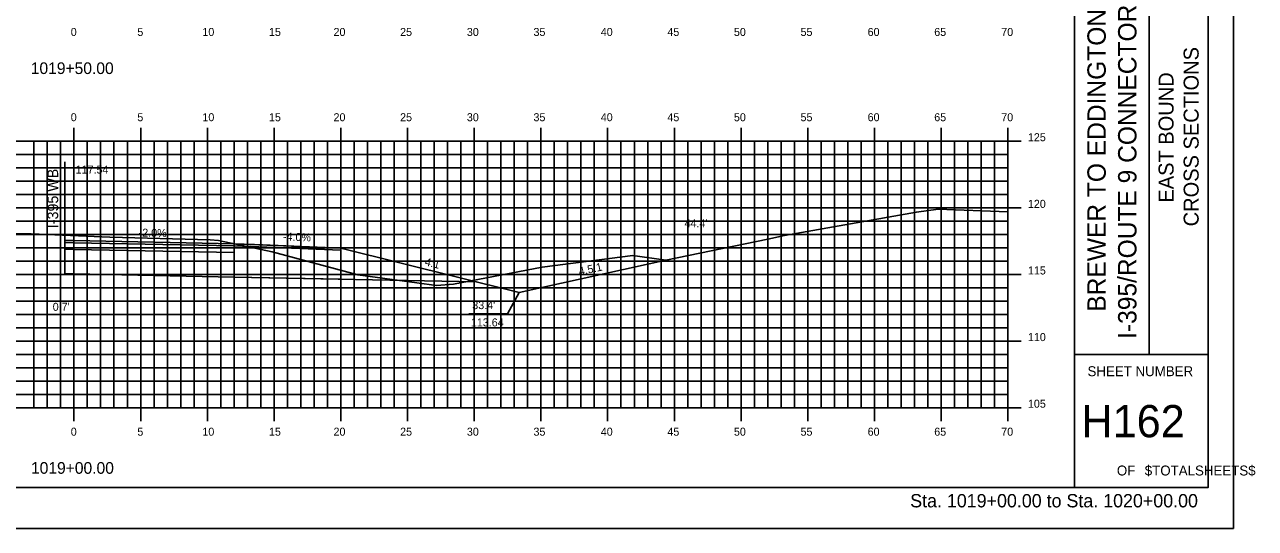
# Model space of a CAD drawing. Extents: x 853734 to 853906, y 365624 to 365734.
# Drawn here: x 853813.6 to 853905.9, y 365624 to 365661.8 of the extents above; entities that cross this region are included whole.
import ezdxf

# ---------------------------------------------------------------- set-up
doc = ezdxf.new("R2010")
doc.units = 0
for name, color, linetype in [('ANNOTATION', 7, 'Continuous'), ('BORDER', 7, 'Continuous'), ('D_Roadway_Centerline', 7, 'Continuous'), ('D_Roadway_Centerline_Text', 7, 'Continuous'), ('D_Roadway_Edge_Shoulder', 7, 'Continuous'), ('D_Roadway_Edge_TW', 7, 'Continuous'), ('D_Roadway_FinishedGrade', 7, 'Continuous'), ('D_Roadway_Pavement', 7, 'Continuous'), ('D_Roadway_SubGrade', 7, 'Continuous'), ('D_Text_Standard', 7, 'Continuous'), ('H_V ANNOTATION', 7, 'Continuous'), ('MAJOR', 7, 'Continuous'), ('MINOR', 7, 'Continuous'), ('PLOT BOUNDARY', 7, 'Continuous'), ('S_Roadway_Centerline', 7, 'Continuous')]:
    doc.layers.add(name, color=color, linetype=linetype)

msp = doc.modelspace()

# ---------------------------------------------------------------- linework, layer by layer
at = {"layer": 'ANNOTATION'}
msp.add_lwpolyline([(853846.938, 365640.065), (853849.826, 365640.065), (853850.691, 365641.67)], dxfattribs=at)
at = {"layer": 'BORDER'}
for p, q in [((853892.331, 365627.027), (853892.331, 365732.027)), ((853897.922, 365637.03), (853897.922, 365672.03)), ((853892.331, 365637.03), (853902.331, 365637.03))]:
    msp.add_line(p, q, dxfattribs=at)
msp.add_lwpolyline([(853742.331, 365627.027), (853902.331, 365627.027), (853902.331, 365732.027), (853742.331, 365732.027)], close=True, dxfattribs=at)
at = {"layer": 'D_Roadway_Centerline'}
for p, q in [((853837.331, 365645.01), (853850.691, 365641.67)), ((853850.691, 365641.67), (853861.699, 365644.103)), ((853829.331, 365642.83), (853847.505, 365642.466))]:
    msp.add_line(p, q, dxfattribs=at)
msp.add_lwpolyline([(853816.655, 365645.584), (853817.235, 365645.572), (853817.331, 365645.57), (853817.332, 365645.57), (853829.331, 365645.33), (853830.854, 365645.269), (853837.326, 365645.01), (853837.331, 365645.01)], dxfattribs=at)
at = {"layer": 'D_Roadway_Edge_Shoulder'}
for points in [[(853817.331, 365645.57), (853816.655, 365645.584), (853816.655, 365645.417), (853817.331, 365645.403)], [(853829.331, 365645.33), (853837.331, 365645.01), (853837.331, 365644.843), (853829.331, 365645.163)]]:
    msp.add_lwpolyline(points, close=True, dxfattribs=at)
at = {"layer": 'D_Roadway_Edge_TW'}
msp.add_lwpolyline([(853817.331, 365645.57), (853829.331, 365645.33), (853829.331, 365645.163), (853817.331, 365645.403)], close=True, dxfattribs=at)
msp.add_lwpolyline([(853829.331, 365645.33), (853829.331, 365645.163)], dxfattribs=at)
at = {"layer": 'D_Roadway_FinishedGrade'}
for p, q in [((853816.655, 365645.584), (853816.655, 365645.334)), ((853817.331, 365645.57), (853817.331, 365645.32)), ((853829.331, 365645.33), (853829.331, 365645.08)), ((853837.331, 365645.01), (853837.331, 365644.76))]:
    msp.add_line(p, q, dxfattribs=at)
at = {"layer": 'D_Roadway_Pavement'}
for points in [[(853817.331, 365645.403), (853816.655, 365645.417), (853816.655, 365644.917), (853817.331, 365644.903)], [(853817.331, 365645.403), (853829.331, 365645.163), (853829.331, 365644.663), (853817.331, 365644.903)]]:
    msp.add_lwpolyline(points, close=True, dxfattribs=at)
msp.add_lwpolyline([(853829.331, 365645.163), (853829.331, 365644.663)], dxfattribs=at)
msp.add_lwpolyline([(853829.331, 365645.163), (853829.331, 365644.663)], dxfattribs=at)
at = {"layer": 'D_Roadway_SubGrade'}
msp.add_line((853816.655, 365651.488), (853816.655, 365643.084), dxfattribs=at)
for points in [[(853817.331, 365644.903), (853816.655, 365644.917), (853816.655, 365645.417), (853816.655, 365645.584), (853816.655, 365643.084), (853817.331, 365643.07)], [(853817.331, 365644.903), (853829.331, 365644.663), (853829.331, 365642.83), (853817.331, 365643.07)], [(853829.331, 365644.663), (853829.331, 365645.163), (853837.331, 365644.843), (853837.331, 365645.01), (853837.331, 365642.67), (853829.331, 365642.83)]]:
    msp.add_lwpolyline(points, close=True, dxfattribs=at)
msp.add_lwpolyline([(853829.331, 365644.663), (853829.331, 365642.83)], dxfattribs=at)
at = {"layer": 'MAJOR'}
for p, q in [((853817.331, 365654.029), (853817.331, 365653.027)), ((853822.331, 365654.029), (853822.331, 365653.027)), ((853827.331, 365654.029), (853827.331, 365653.027)), ((853832.331, 365654.029), (853832.331, 365653.027)), ((853837.331, 365654.029), (853837.331, 365653.027)), ((853842.331, 365654.029), (853842.331, 365653.027)), ((853847.331, 365654.029), (853847.331, 365653.027)), ((853852.331, 365654.029), (853852.331, 365653.027)), ((853857.331, 365654.029), (853857.331, 365653.027)), ((853862.331, 365654.029), (853862.331, 365653.027)), ((853867.331, 365654.029), (853867.331, 365653.027)), ((853872.331, 365654.029), (853872.331, 365653.027)), ((853877.331, 365654.029), (853877.331, 365653.027)), ((853882.331, 365654.029), (853882.331, 365653.027)), ((853887.331, 365654.029), (853887.331, 365653.027)), ((853747.331, 365653.027), (853887.331, 365653.027)), ((853747.331, 365653.027), (853887.331, 365653.027)), ((853817.331, 365633.027), (853817.331, 365653.027)), ((853822.331, 365633.027), (853822.331, 365653.027)), ((853827.331, 365633.027), (853827.331, 365653.027)), ((853832.331, 365633.027), (853832.331, 365653.027)), ((853837.331, 365633.027), (853837.331, 365653.027)), ((853842.331, 365633.027), (853842.331, 365653.027)), ((853847.331, 365633.027), (853847.331, 365653.027)), ((853852.331, 365633.027), (853852.331, 365653.027)), ((853857.331, 365633.027), (853857.331, 365653.027)), ((853862.331, 365633.027), (853862.331, 365653.027)), ((853867.331, 365633.027), (853867.331, 365653.027)), ((853872.331, 365633.027), (853872.331, 365653.027)), ((853877.331, 365633.027), (853877.331, 365653.027)), ((853882.331, 365633.027), (853882.331, 365653.027)), ((853888.333, 365653.027), (853886.329, 365653.027)), ((853887.331, 365633.027), (853887.331, 365653.027)), ((853887.331, 365633.027), (853887.331, 365653.027)), ((853747.331, 365648.027), (853887.331, 365648.027)), ((853888.333, 365648.027), (853886.329, 365648.027)), ((853747.331, 365643.027), (853887.331, 365643.027)), ((853888.333, 365643.027), (853886.329, 365643.027)), ((853747.331, 365638.027), (853887.331, 365638.027)), ((853888.333, 365638.027), (853886.329, 365638.027)), ((853747.331, 365633.027), (853887.331, 365633.027)), ((853747.331, 365633.027), (853887.331, 365633.027)), ((853817.331, 365632.025), (853817.331, 365633.027)), ((853822.331, 365632.025), (853822.331, 365633.027)), ((853827.331, 365632.025), (853827.331, 365633.027)), ((853832.331, 365632.025), (853832.331, 365633.027)), ((853837.331, 365632.025), (853837.331, 365633.027)), ((853842.331, 365632.025), (853842.331, 365633.027)), ((853847.331, 365632.025), (853847.331, 365633.027)), ((853852.331, 365632.025), (853852.331, 365633.027)), ((853857.331, 365632.025), (853857.331, 365633.027)), ((853862.331, 365632.025), (853862.331, 365633.027)), ((853867.331, 365632.025), (853867.331, 365633.027)), ((853872.331, 365632.025), (853872.331, 365633.027)), ((853877.331, 365632.025), (853877.331, 365633.027)), ((853882.331, 365632.025), (853882.331, 365633.027)), ((853888.333, 365633.027), (853886.329, 365633.027)), ((853887.331, 365632.025), (853887.331, 365633.027))]:
    msp.add_line(p, q, dxfattribs=at)
at = {"layer": 'MINOR'}
for p, q in [((853814.331, 365633.027), (853814.331, 365653.027)), ((853815.331, 365633.027), (853815.331, 365653.027)), ((853816.331, 365633.027), (853816.331, 365653.027)), ((853818.331, 365633.027), (853818.331, 365653.027)), ((853819.331, 365633.027), (853819.331, 365653.027)), ((853820.331, 365633.027), (853820.331, 365653.027)), ((853821.331, 365633.027), (853821.331, 365653.027)), ((853823.331, 365633.027), (853823.331, 365653.027)), ((853824.331, 365633.027), (853824.331, 365653.027)), ((853825.331, 365633.027), (853825.331, 365653.027)), ((853826.331, 365633.027), (853826.331, 365653.027)), ((853828.331, 365633.027), (853828.331, 365653.027)), ((853829.331, 365633.027), (853829.331, 365653.027)), ((853830.331, 365633.027), (853830.331, 365653.027)), ((853831.331, 365633.027), (853831.331, 365653.027)), ((853833.331, 365633.027), (853833.331, 365653.027)), ((853834.331, 365633.027), (853834.331, 365653.027)), ((853835.331, 365633.027), (853835.331, 365653.027)), ((853836.331, 365633.027), (853836.331, 365653.027)), ((853838.331, 365633.027), (853838.331, 365653.027)), ((853839.331, 365633.027), (853839.331, 365653.027)), ((853840.331, 365633.027), (853840.331, 365653.027)), ((853841.331, 365633.027), (853841.331, 365653.027)), ((853843.331, 365633.027), (853843.331, 365653.027)), ((853844.331, 365633.027), (853844.331, 365653.027)), ((853845.331, 365633.027), (853845.331, 365653.027)), ((853846.331, 365633.027), (853846.331, 365653.027)), ((853848.331, 365633.027), (853848.331, 365653.027)), ((853849.331, 365633.027), (853849.331, 365653.027)), ((853850.331, 365633.027), (853850.331, 365653.027)), ((853851.331, 365633.027), (853851.331, 365653.027)), ((853853.331, 365633.027), (853853.331, 365653.027)), ((853854.331, 365633.027), (853854.331, 365653.027)), ((853855.331, 365633.027), (853855.331, 365653.027)), ((853856.331, 365633.027), (853856.331, 365653.027)), ((853858.331, 365633.027), (853858.331, 365653.027)), ((853859.331, 365633.027), (853859.331, 365653.027)), ((853860.331, 365633.027), (853860.331, 365653.027)), ((853861.331, 365633.027), (853861.331, 365653.027)), ((853863.331, 365633.027), (853863.331, 365653.027)), ((853864.331, 365633.027), (853864.331, 365653.027)), ((853865.331, 365633.027), (853865.331, 365653.027)), ((853866.331, 365633.027), (853866.331, 365653.027)), ((853868.331, 365633.027), (853868.331, 365653.027)), ((853869.331, 365633.027), (853869.331, 365653.027)), ((853870.331, 365633.027), (853870.331, 365653.027)), ((853871.331, 365633.027), (853871.331, 365653.027)), ((853873.331, 365633.027), (853873.331, 365653.027)), ((853874.331, 365633.027), (853874.331, 365653.027)), ((853875.331, 365633.027), (853875.331, 365653.027)), ((853876.331, 365633.027), (853876.331, 365653.027)), ((853878.331, 365633.027), (853878.331, 365653.027)), ((853879.331, 365633.027), (853879.331, 365653.027)), ((853880.331, 365633.027), (853880.331, 365653.027)), ((853881.331, 365633.027), (853881.331, 365653.027)), ((853883.331, 365633.027), (853883.331, 365653.027)), ((853884.331, 365633.027), (853884.331, 365653.027)), ((853885.331, 365633.027), (853885.331, 365653.027)), ((853886.331, 365633.027), (853886.331, 365653.027)), ((853747.331, 365652.027), (853887.331, 365652.027)), ((853887.331, 365652.027), (853886.329, 365652.027)), ((853747.331, 365651.027), (853887.331, 365651.027)), ((853887.331, 365651.027), (853886.329, 365651.027)), ((853747.331, 365650.027), (853887.331, 365650.027)), ((853887.331, 365650.027), (853886.329, 365650.027)), ((853747.331, 365649.027), (853887.331, 365649.027)), ((853887.331, 365649.027), (853886.329, 365649.027)), ((853747.331, 365647.027), (853887.331, 365647.027)), ((853887.331, 365647.027), (853886.329, 365647.027)), ((853747.331, 365646.027), (853887.331, 365646.027)), ((853887.331, 365646.027), (853886.329, 365646.027)), ((853747.331, 365645.027), (853887.331, 365645.027)), ((853887.331, 365645.027), (853886.329, 365645.027)), ((853747.331, 365644.027), (853887.331, 365644.027)), ((853887.331, 365644.027), (853886.329, 365644.027)), ((853747.331, 365642.027), (853887.331, 365642.027)), ((853887.331, 365642.027), (853886.329, 365642.027)), ((853747.331, 365641.027), (853887.331, 365641.027)), ((853887.331, 365641.027), (853886.329, 365641.027)), ((853747.331, 365640.027), (853887.331, 365640.027)), ((853887.331, 365640.027), (853886.329, 365640.027)), ((853747.331, 365639.027), (853887.331, 365639.027)), ((853887.331, 365639.027), (853886.329, 365639.027)), ((853747.331, 365637.027), (853887.331, 365637.027)), ((853887.331, 365637.027), (853886.329, 365637.027)), ((853747.331, 365636.027), (853887.331, 365636.027)), ((853887.331, 365636.027), (853886.329, 365636.027)), ((853747.331, 365635.027), (853887.331, 365635.027)), ((853887.331, 365635.027), (853886.329, 365635.027)), ((853747.331, 365634.027), (853887.331, 365634.027)), ((853887.331, 365634.027), (853886.329, 365634.027))]:
    msp.add_line(p, q, dxfattribs=at)
at = {"layer": 'PLOT BOUNDARY'}
msp.add_lwpolyline([(853734.238, 365623.968), (853904.238, 365623.968), (853904.238, 365733.968), (853734.238, 365733.968)], close=True, dxfattribs=at)
at = {"layer": 'S_Roadway_Centerline'}
msp.add_lwpolyline([(853811.758, 365646.1), (853814.129, 365646.084), (853820.011, 365645.83), (853827.546, 365645.616), (853828.156, 365645.568), (853832.174, 365644.736), (853838.611, 365643.01), (853844.496, 365642.206), (853845.777, 365642.301), (853852.416, 365643.573), (853859.214, 365644.439), (853861.699, 365644.103), (853869.342, 365645.676), (853870.576, 365645.939), (853880.472, 365647.706), (853882.115, 365647.939), (853887.331, 365647.726)], dxfattribs=at)

# ---------------------------------------------------------------- texts
at = {"layer": 'ANNOTATION'}
for s, height, rotation, p in [('I-395 WB', 0.8, 90, (853816.148, 365646.502)), ('-2.0%', 0.6, 358.8542, (853822.175, 365645.873)), ('-4.0%', 0.6, 357.70937, (853832.986, 365645.584)), ('4:1', 0.6, 345.96376, (853843.586, 365643.721)), ('4.5:1', 0.6, 12.46619, (853855.227, 365642.946)), ("33.4' ", 0.6, 360, (853847.186, 365640.428)), ('113.64', 0.6, 360, (853847.081, 365639.128))]:
    msp.add_text(s, height=height, rotation=rotation, dxfattribs=at).set_placement(p)
at = {"layer": 'BORDER'}
for s, height, p in [('BREWER TO EDDINGTON', 1.37787, (853894.665, 365640.231)), ('I-395/ROUTE 9 CONNECTOR', 1.37787, (853896.966, 365638.192)), ('CROSS SECTIONS', 1.125, (853901.628, 365646.638)), ('EAST BOUND', 1.125, (853899.749, 365648.418))]:
    msp.add_text(s, height=height, rotation=90, dxfattribs=at).set_placement(p)
for s, height, p in [('SHEET NUMBER', 0.74527, (853893.297, 365635.393)), ('H162', 2.4194, (853892.847, 365630.809)), ('OF', 0.7453, (853895.498, 365627.94)), ('$TOTALSHEETS$', 0.74527, (853897.588, 365627.94))]:
    msp.add_text(s, height=height, dxfattribs=at).set_placement(p)
at = {"layer": 'D_Roadway_Centerline'}
for s, p in [('C', (853817.326, 365645.57)), ('L', (853817.331, 365645.562))]:
    msp.add_text(s, height=0.0146, dxfattribs=at).set_placement(p)
at = {"layer": 'D_Roadway_Centerline_Text'}
msp.add_text('117.54', height=0.6, dxfattribs=at).set_placement((853817.459, 365650.602))
at = {"layer": 'D_Text_Standard'}
for s, p in [("44.4'", (853863.097, 365646.576)), ("0.7'", (853815.738, 365640.301))]:
    msp.add_text(s, height=0.6, dxfattribs=at).set_placement(p)
at = {"layer": 'H_V ANNOTATION'}
for s, height, p in [('0', 0.6, (853817.09, 365660.927)), ('5', 0.6, (853822.082, 365660.927)), ('10', 0.6, (853826.956, 365660.927)), ('15', 0.6, (853831.948, 365660.927)), ('20', 0.6, (853836.785, 365660.927)), ('25', 0.6, (853841.777, 365660.927)), ('30', 0.6, (853846.78, 365660.927)), ('35', 0.6, (853851.772, 365660.927)), ('40', 0.6, (853856.817, 365660.927)), ('45', 0.6, (853861.809, 365660.927)), ('50', 0.6, (853866.796, 365660.927)), ('55', 0.6, (853871.788, 365660.927)), ('60', 0.6, (853876.817, 365660.927)), ('65', 0.6, (853881.809, 365660.927)), ('70', 0.6, (853886.833, 365660.927)), ('1019+50.00', 0.875, (853814.093, 365658.07)), ('0', 0.6, (853817.09, 365654.527)), ('5', 0.6, (853822.082, 365654.527)), ('10', 0.6, (853826.956, 365654.527)), ('15', 0.6, (853831.948, 365654.527)), ('20', 0.6, (853836.785, 365654.527)), ('25', 0.6, (853841.777, 365654.527)), ('30', 0.6, (853846.78, 365654.527)), ('35', 0.6, (853851.772, 365654.527)), ('40', 0.6, (853856.817, 365654.527)), ('45', 0.6, (853861.809, 365654.527)), ('50', 0.6, (853866.796, 365654.527)), ('55', 0.6, (853871.788, 365654.527)), ('60', 0.6, (853876.817, 365654.527)), ('65', 0.6, (853881.809, 365654.527)), ('70', 0.6, (853886.833, 365654.527)), ('125', 0.6, (853888.831, 365653.027)), ('120', 0.6, (853888.831, 365648.027)), ('115', 0.6, (853888.831, 365643.027)), ('110', 0.6, (853888.831, 365638.027)), ('105', 0.6, (853888.831, 365633.027)), ('0', 0.6, (853817.09, 365630.927)), ('5', 0.6, (853822.082, 365630.927)), ('10', 0.6, (853826.956, 365630.927)), ('15', 0.6, (853831.948, 365630.927)), ('20', 0.6, (853836.785, 365630.927)), ('25', 0.6, (853841.777, 365630.927)), ('30', 0.6, (853846.78, 365630.927)), ('35', 0.6, (853851.772, 365630.927)), ('40', 0.6, (853856.817, 365630.927)), ('45', 0.6, (853861.809, 365630.927)), ('50', 0.6, (853866.796, 365630.927)), ('55', 0.6, (853871.788, 365630.927)), ('60', 0.6, (853876.817, 365630.927)), ('65', 0.6, (853881.809, 365630.927)), ('70', 0.6, (853886.833, 365630.927)), ('1019+00.00', 0.875, (853814.109, 365628.07)), ('Sta. 1019+00.00 to Sta. 1020+00.00', 1.0002, (853880.007, 365625.547))]:
    msp.add_text(s, height=height, dxfattribs=at).set_placement(p)

doc.saveas('drawing.dxf')
